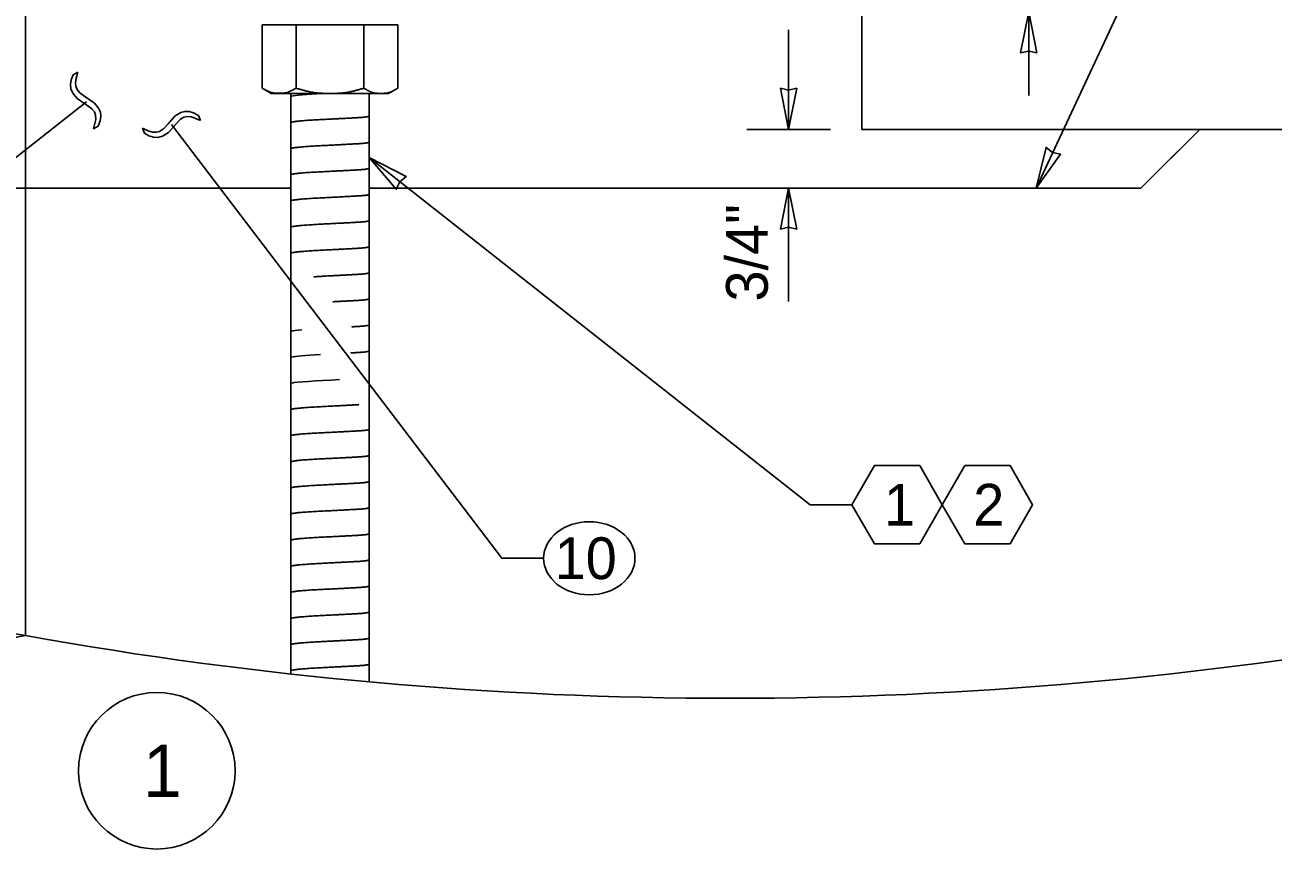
# Model space of a CAD drawing. Extents: x 99862 to 103151, y 100000 to 102076.
# Drawn here: x 101466.5 to 101944.8, y 101181.5 to 101497.3 of the extents above; entities that cross this region are included whole.
import ezdxf

# ---------------------------------------------------------------- set-up
doc = ezdxf.new("R2010")
doc.units = 0
for name, color, linetype in [('Level 12', 7, 'Continuous'), ('Level 15', 7, 'Continuous'), ('Level 20', 7, 'Continuous'), ('Level 6', 7, 'Continuous'), ('Level 62', 7, 'Continuous'), ('Level 9', 7, 'Continuous')]:
    doc.layers.add(name, color=color, linetype=linetype)

msp = doc.modelspace()

# ---------------------------------------------------------------- linework, layer by layer
at = {"layer": 'Level 12'}
for p, q in [((101894.17, 101434.82), (101916.67, 101457.32)), ((101916.67, 101457.32), (101984.17, 101457.32)), ((101039.17, 101434.82), (101568.33, 101434.82)), ((101598.33, 101434.82), (101894.17, 101434.82))]:
    msp.add_line(p, q, dxfattribs=at)
for centre, start, end in [((101196.67, 99756.55), 79.84079, 100.15921), ((101196.67, 102770.06), 259.84079, 280.15921), ((101736.67, 102770.06), 259.84079, 280.15921)]:
    msp.add_arc(centre, 1530.75, start, end, dxfattribs=at)
at = {"layer": 'Level 15'}
for p, q in [((101853.94, 101434.82), (101971.9, 101687.2)), ((101851.14, 101470.32), (101851.14, 101502.32)), ((101759.14, 101457.32), (101759.14, 101495.52)), ((101490.02, 101467.81), (101377.26, 101379.4)), ((101649.23, 101292.97), (101522.61, 101459.21)), ((101775.14, 101457.32), (101743.14, 101457.32)), ((101916.67, 101457.32), (101900.76, 101441.41)), ((101767.39, 101313.47), (101598.33, 101446.53)), ((101759.14, 101434.82), (101759.14, 101391.34)), ((101767.39, 101313.47), (101783.39, 101313.47)), ((101649.23, 101292.97), (101665.23, 101292.97))]:
    msp.add_line(p, q, dxfattribs=at)
for points in [[(101851.14, 101502.32), (101848.06, 101486.6), (101851.14, 101487.33), (101854.23, 101486.6)], [(101759.14, 101457.32), (101756.06, 101473.05), (101759.14, 101472.32), (101762.23, 101473.05)], [(101853.94, 101434.82), (101857.81, 101450.37), (101860.29, 101448.41), (101863.39, 101447.76)], [(101598.33, 101446.53), (101608.78, 101434.38), (101610.11, 101437.25), (101612.59, 101439.23)], [(101759.14, 101434.82), (101756.06, 101419.1), (101759.14, 101419.83), (101762.23, 101419.1)]]:
    msp.add_lwpolyline(points, close=True, dxfattribs=at)
at = {"layer": 'Level 20'}
for p, q in [((101484.95, 101478.15), (101484.18, 101476.32)), ((101486.78, 101479.21), (101484.95, 101478.15)), ((101486.04, 101476.9), (101486.78, 101479.21)), ((101484.18, 101476.32), (101483.89, 101474.55)), ((101483.89, 101474.55), (101484.09, 101472.86)), ((101484.09, 101472.86), (101484.76, 101471.23)), ((101485.77, 101475.19), (101486.04, 101476.9)), ((101485.92, 101473.83), (101485.77, 101475.19)), ((101486.41, 101472.6), (101485.92, 101473.83)), ((101487.67, 101471.14), (101486.41, 101472.6)), ((101484.76, 101471.23), (101486.51, 101469.15)), ((101486.51, 101469.15), (101490.13, 101466.62)), ((101489.76, 101469.68), (101487.67, 101471.14)), ((101493.16, 101467.41), (101489.76, 101469.68)), ((101490.13, 101466.62), (101492.12, 101465.24)), ((101492.12, 101465.24), (101493.07, 101464.08)), ((101493.07, 101464.08), (101493.55, 101462.74)), ((101494.7, 101465.48), (101493.16, 101467.41)), ((101495.35, 101463.95), (101494.7, 101465.48)), ((101495.53, 101462.35), (101495.35, 101463.95)), ((101526.14, 101463.77), (101524.02, 101462.5)), ((101527.74, 101464.21), (101526.14, 101463.77)), ((101529.36, 101464.17), (101527.74, 101464.21)), ((101531.06, 101463.67), (101529.36, 101464.17)), ((101532.96, 101462.66), (101531.06, 101463.67)), ((101493.61, 101461.09), (101492.68, 101457.52)), ((101492.68, 101457.52), (101494.51, 101458.58)), ((101493.55, 101462.74), (101493.61, 101461.09)), ((101494.51, 101458.57), (101495.26, 101460.59)), ((101495.26, 101460.59), (101495.53, 101462.35)), ((101521.32, 101459.43), (101519.59, 101457.56)), ((101524.02, 101462.5), (101521.32, 101459.43)), ((101521.41, 101456.15), (101524.39, 101459.4)), ((101524.39, 101459.4), (101526.03, 101461.19)), ((101526.03, 101461.19), (101527.31, 101461.97)), ((101527.31, 101461.97), (101528.7, 101462.27)), ((101528.7, 101462.27), (101530.34, 101462.1)), ((101530.34, 101462.1), (101533.76, 101460.7)), ((101533.76, 101460.7), (101532.96, 101462.66)), ((101513.66, 101456.72), (101511.47, 101457.76)), ((101511.47, 101457.76), (101512.27, 101455.81)), ((101512.27, 101455.81), (101513.99, 101454.8)), ((101515.32, 101456.22), (101513.66, 101456.72)), ((101513.99, 101454.8), (101515.7, 101454.28)), ((101516.68, 101456.19), (101515.32, 101456.22)), ((101515.7, 101454.28), (101517.41, 101454.24)), ((101517.98, 101456.51), (101516.68, 101456.19)), ((101517.41, 101454.24), (101519.11, 101454.69)), ((101519.59, 101457.56), (101517.98, 101456.51)), ((101519.11, 101454.69), (101521.41, 101456.15))]:
    msp.add_line(p, q, dxfattribs=at)
for points in [[(101783.39, 101313.47), (101792.05, 101328.47), (101809.37, 101328.47), (101818.02, 101313.47), (101809.37, 101298.48), (101792.05, 101298.48), (101783.39, 101313.47)], [(101818.02, 101313.47), (101826.68, 101328.47), (101844, 101328.47), (101852.64, 101313.47), (101844, 101298.48), (101826.68, 101298.48), (101818.02, 101313.47)]]:
    msp.add_lwpolyline(points, dxfattribs=at)
msp.add_ellipse((101682.73, 101292.97), major_axis=(-17.5, 0), ratio=0.8, dxfattribs=at)
at = {"layer": 'Level 6'}
for p, q in [((101787.14, 101532.32), (101787.14, 101457.32)), ((101598.52, 101456.97), (101598.33, 101456.93)), ((101787.14, 101457.32), (101916.67, 101457.32))]:
    msp.add_line(p, q, dxfattribs=at)
at = {"layer": 'Level 62'}
for points, degree in [([(101568.33, 101470.45), (101568.28, 101470.42), (101568.28, 101470.39), (101568.33, 101470.36)], 3), ([(101580.45, 101471.07), (101574.2, 101470.7), (101569.93, 101470.36), (101568.69, 101470.07)], 3), ([(101568.33, 101465.48), (101568.26, 101465.44), (101568.25, 101465.4), (101568.33, 101465.36)], 3), ([(101568.33, 101460.47), (101568.29, 101460.44), (101568.29, 101460.41), (101568.33, 101460.38)], 3), ([(101597.94, 101462.23), (101596.97, 101461.99), (101594.5, 101461.8), (101591.26, 101461.64), (101581.75, 101461.15), (101571.12, 101460.64), (101568.69, 101460.1)], 4), ([(101597.94, 101452.24), (101597.02, 101452.01), (101594.74, 101451.83), (101591.74, 101451.68), (101582.18, 101451.17), (101571.18, 101450.63), (101568.69, 101450.09)], 4), ([(101597.94, 101442.22), (101597.07, 101442.01), (101594.99, 101441.83), (101592.22, 101441.69), (101582.6, 101441.16), (101571.23, 101440.67), (101568.69, 101440.1)], 4), ([(101598.31, 101432.35), (101597.91, 101432.1), (101595.78, 101431.89), (101592.67, 101431.73), (101583.05, 101431.19), (101571.36, 101430.66), (101568.69, 101430.09)], 4), ([(101597.94, 101422.16), (101597.02, 101421.93), (101594.74, 101421.75), (101591.74, 101421.6), (101582.18, 101421.09), (101571.18, 101420.55), (101568.69, 101420)], 4), ([(101597.94, 101412.17), (101597.02, 101411.95), (101594.74, 101411.76), (101591.74, 101411.61), (101582.18, 101411.1), (101571.18, 101410.56), (101568.69, 101410.02)], 4), ([(101597.94, 101402.19), (101597.02, 101401.96), (101594.74, 101401.78), (101591.74, 101401.63), (101587.55, 101401.4), (101582.25, 101401.13), (101577.16, 101400.8)], 4), ([(101597.94, 101392.2), (101597.02, 101391.98), (101594.74, 101391.79), (101591.74, 101391.64), (101589.63, 101391.53), (101587.15, 101391.4), (101584.43, 101391.25)], 4), ([(101597.94, 101382.22), (101597.02, 101381.99), (101594.74, 101381.81), (101591.74, 101381.66), (101591.74, 101381.66), (101591.74, 101381.66), (101591.74, 101381.66)], 4), ([(101572.51, 101380.49), (101570.52, 101380.33), (101569.26, 101380.19), (101568.69, 101380.07)], 3), ([(101597.94, 101372.23), (101597.02, 101372.01), (101594.74, 101371.82), (101591.74, 101371.67), (101591.63, 101371.67), (101591.51, 101371.66), (101591.4, 101371.65)], 4), ([(101579.73, 101371.01), (101573.81, 101370.65), (101569.88, 101370.34), (101568.69, 101370.08)], 3), ([(101587.05, 101361.41), (101578.04, 101360.93), (101570.53, 101360.5), (101568.69, 101360.1)], 3), ([(101594.35, 101351.82), (101593.82, 101351.79), (101593.26, 101351.75), (101592.67, 101351.72), (101583.05, 101351.18), (101571.36, 101350.65), (101568.69, 101350.08)], 4), ([(101598.31, 101342.33), (101597.87, 101342.05), (101595.46, 101341.83), (101591.98, 101341.64), (101582.38, 101341.12), (101571.19, 101340.63), (101568.69, 101340.07)], 4), ([(101597.94, 101332.2), (101597.09, 101331.99), (101595.09, 101331.82), (101592.43, 101331.68), (101582.81, 101331.15), (101571.28, 101330.65), (101568.69, 101330.06)], 4), ([(101597.94, 101322.19), (101597.02, 101321.96), (101594.74, 101321.78), (101591.74, 101321.63), (101582.18, 101321.12), (101571.18, 101320.58), (101568.69, 101320.04)], 4), ([(101597.94, 101312.17), (101597.07, 101311.95), (101594.99, 101311.78), (101592.22, 101311.64), (101582.6, 101311.11), (101571.23, 101310.61), (101568.69, 101310.05)], 4), ([(101597.94, 101302.18), (101597.09, 101301.97), (101595.09, 101301.8), (101592.43, 101301.66), (101582.81, 101301.13), (101571.28, 101300.63), (101568.69, 101300.04)], 4), ([(101597.94, 101292.17), (101597.02, 101291.95), (101594.74, 101291.76), (101591.74, 101291.61), (101582.18, 101291.1), (101571.18, 101290.56), (101568.69, 101290.02)], 4), ([(101597.94, 101282.15), (101597.07, 101281.94), (101594.99, 101281.77), (101592.22, 101281.62), (101582.6, 101281.1), (101571.23, 101280.6), (101568.69, 101280.04)], 4), ([(101597.94, 101272.17), (101597.02, 101271.94), (101594.74, 101271.76), (101591.74, 101271.61), (101582.18, 101271.1), (101571.18, 101270.56), (101568.69, 101270.02)], 4), ([(101597.94, 101262.18), (101597.01, 101261.95), (101594.74, 101261.77), (101591.74, 101261.62), (101582.18, 101261.11), (101571.18, 101260.57), (101568.69, 101260.03)], 4), ([(101597.94, 101252.19), (101597.01, 101251.96), (101594.74, 101251.78), (101591.74, 101251.63), (101582.18, 101251.12), (101571.18, 101250.58), (101568.69, 101250.03)], 4)]:
    msp.add_open_spline(points, degree=degree, dxfattribs=at)
at = {"layer": 'Level 9'}
for p, q in [((101466.67, 101869.87), (101466.67, 101263.31)), ((101557.36, 101497.32), (101609.31, 101497.32)), ((101557.36, 101473.08), (101557.36, 101497.32)), ((101570.35, 101473.08), (101570.35, 101497.32)), ((101596.33, 101473.08), (101596.33, 101497.32)), ((101609.31, 101473.08), (101609.31, 101497.32)), ((101557.36, 101473.08), (101560.84, 101471.07)), ((101605.84, 101471.07), (101609.31, 101473.08)), ((101568.33, 101471.07), (101560.84, 101471.07)), ((101598.33, 101471.07), (101568.33, 101471.07)), ((101568.33, 101471.07), (101568.33, 101248.59)), ((101602.59, 101471.07), (101598.33, 101471.07)), ((101598.33, 101245.57), (101598.33, 101471.07)), ((101602.59, 101471.07), (101603.06, 101471.07)), ((101605.84, 101471.07), (101603.06, 101471.07))]:
    msp.add_line(p, q, dxfattribs=at)
msp.add_circle((101516.99, 101211.53), 30, dxfattribs=at)
for points, degree in [([(101557.36, 101473.08), (101559.48, 101471.86), (101561.63, 101471.08), (101566.05, 101471.07), (101568.23, 101471.86), (101570.35, 101473.08)], 3), ([(101583.34, 101471.07), (101578.94, 101471.07), (101574.55, 101471.87), (101570.35, 101473.08)], 2), ([(101596.33, 101473.08), (101592.1, 101471.86), (101587.73, 101471.07), (101583.34, 101471.07)], 2), ([(101596.33, 101473.08), (101598.38, 101471.9), (101600.46, 101471.12), (101602.59, 101471.07)], 2), ([(101603.06, 101471.07), (101605.19, 101471.12), (101607.27, 101471.9), (101609.31, 101473.08)], 2)]:
    msp.add_open_spline(points, degree=degree, dxfattribs=at)

# ---------------------------------------------------------------- texts
at = {"layer": 'Level 20'}
msp.add_text('3/4"', height=16, rotation=90, dxfattribs=at).set_placement((101751.14, 101391.34))
for s, height, p in [('1', 16, (101795.73, 101305.47)), ('2', 16, (101829.9, 101305.47)), ('10', 16, (101669.47, 101284.97)), ('1', 20, (101511.71, 101201.53))]:
    msp.add_text(s, height=height, dxfattribs=at).set_placement(p)

doc.saveas('drawing.dxf')
